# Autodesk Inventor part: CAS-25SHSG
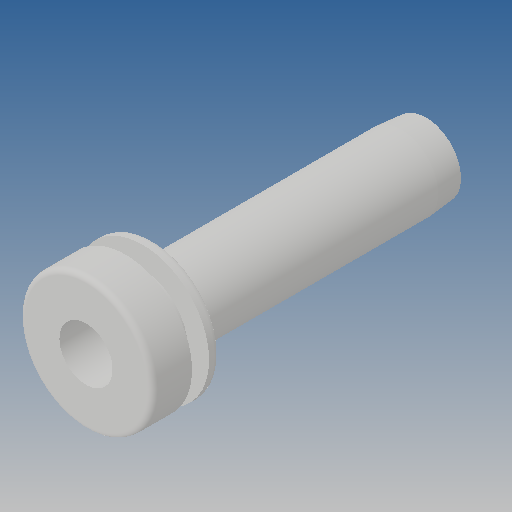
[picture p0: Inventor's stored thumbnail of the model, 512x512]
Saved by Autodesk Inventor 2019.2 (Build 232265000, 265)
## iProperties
Created: 2010-02
Part Number: CAS-25SHSG
Material: Ogólny
Document SubType Name: Modeling
Designer: CADENGINEERING4
Density: 1 g/cm^3
Appearance: Domyślna
Author: CADENGINEERING4
Revision Number: 1LAST_VERSION
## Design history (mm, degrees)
feature "Baza1"
node "Bryła1"
